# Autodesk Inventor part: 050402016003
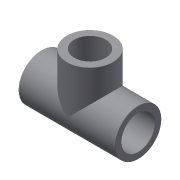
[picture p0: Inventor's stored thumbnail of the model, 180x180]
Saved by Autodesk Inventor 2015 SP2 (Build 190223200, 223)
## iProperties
Created: 2017-10
Part Number: 050402016003
Material: Generic
Description: PLASSON TEE THR-CEM PVC 16-3/8"
Document SubType Name: Modeling
Designer: KIM
Density: 1 g/cm^3
Appearance: Default
Author: KIM
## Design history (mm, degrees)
derived "050402.ipt"
feature "Solid1::050402.ipt"
feature "Solid2::050402.ipt"
tag "TaggingFeature1"
body "Solid1"
other parameters: "d0" = 46, "d1" = 22, "d2" = 14, "d4" = 16, "d5" = 13.455, "d7" = 0.1495, "d8" = 14, "d9" = 23, "d10" = 22, "d15" = 0, "d18" = 14.95, "d24" = 0.1495, "d30" = 14.95, "d31" = 13, "d32" = 0, "d33" = 13.455, "d35" = 0, "G_" = 14.95, "E_" = 22, "H_" = 46, "lt_" = 13, "l_" = 14, "h_" = 23, "d_" = 16
